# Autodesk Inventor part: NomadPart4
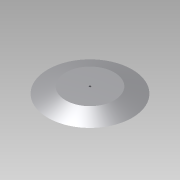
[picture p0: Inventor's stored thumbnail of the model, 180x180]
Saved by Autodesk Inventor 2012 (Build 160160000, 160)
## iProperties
Created: 2012-10
Part Number: NomadPart4
Material: Default
Document SubType Name: Modeling
Designer: TechShop Member
Density: 1 g/cm^3
Author: TechShop Member
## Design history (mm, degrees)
sketch "Sketch1"
  geometry: L1 (0, 0)-(105.791, 0); L2 (105.791, 0)-(0, 0); L3 (0, 0)-(0, 15.875); L4 (0, 15.875)-(61.138, 15.875); L5 (61.138, 15.875)-(105.791, 0)
  constraints: 10 end point, 2 perpendicular, 1 collinear, 1 horizontal
  dimensions: "d0" = 105.791 distance of L1.start L1.end; "d1" = 15.875 distance of L1.start L3.end; "d2" = 61.1378 distance of L3.end L4.end
revolve "Revolution1" sketch "Sketch1" stored, may be unused: angle "d3" = 90 deg
sketch "Sketch2"
  geometry: C1 r 61.138 at (0, 0) reference; 1 further point
  constraints: 1 coincident
hole "Hole1" sketch "Sketch2" at (0, 0) diameter "d4" = 5.207; stored, may be unused: countersink angle "d8" = 82 deg, drill point angle "d10" = 118 deg; dims "d5" = 19.05, "d6" = 9.525, "d7" = 6.35, "d9" = 25.4
body "Solid1"
